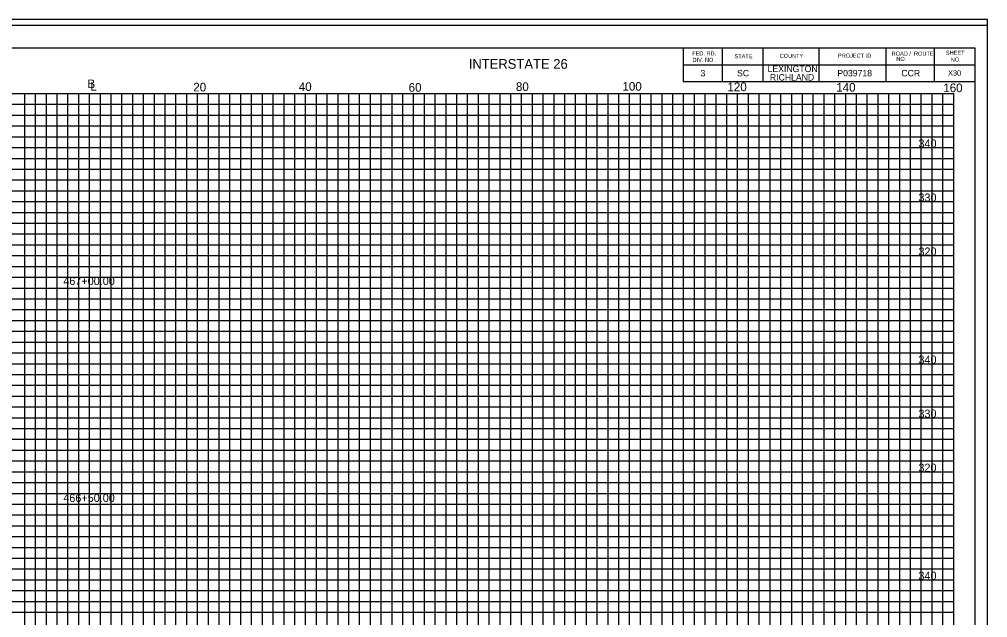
# Model space of a CAD drawing. Extents: x 967 to 1746, y 964 to 7904.
# Drawn here: x 1567 to 1746.3, y 1353 to 1463.7 of the extents above; entities that cross this region are included whole.
import ezdxf

# ---------------------------------------------------------------- set-up
doc = ezdxf.new("R2010")
doc.units = 0
for name, color, linetype in [('Default', 7, 'Continuous'), ('RD_SHT_Bndy', 7, 'Continuous'), ('RD_SHT_IplotShp', 7, 'Continuous'), ('RD_SHT_MjGrid', 7, 'Continuous'), ('RD_SHT_MnGrid', 7, 'Continuous'), ('RD_SHT_TX', 7, 'Continuous'), ('RD_Sketch1', 7, 'Continuous')]:
    doc.layers.add(name, color=color, linetype=linetype)

msp = doc.modelspace()

# ---------------------------------------------------------------- linework, layer by layer
at = {"layer": 'RD_SHT_Bndy'}
for p, q in [((1416.11, 1458.46), (1743.89, 1458.46)), ((1689.89, 1458.46), (1689.89, 1452.21)), ((1697.14, 1458.46), (1697.14, 1452.21)), ((1704.64, 1458.46), (1704.64, 1452.21)), ((1715, 1458.46), (1715, 1452.21)), ((1727.43, 1458.46), (1727.43, 1452.21)), ((1736.39, 1458.46), (1736.39, 1452.21)), ((1743.89, 1458.46), (1743.89, 1248.98)), ((1689.89, 1455.33), (1743.89, 1455.33)), ((1689.89, 1452.21), (1743.89, 1452.21))]:
    msp.add_line(p, q, dxfattribs=at)
at = {"layer": 'RD_SHT_IplotShp'}
for points in [[(1387.41, 1243.72), (1746.28, 1243.72), (1746.28, 1463.72), (1387.41, 1463.72)], [(1408.52, 1244.84), (1746.28, 1244.84), (1746.28, 1462.6), (1408.52, 1462.6)]]:
    msp.add_lwpolyline(points, close=True, dxfattribs=at)
at = {"layer": 'RD_SHT_MjGrid'}
for p, q in [((1420, 1450), (1740, 1450)), ((1570, 1280), (1570, 1450)), ((1580, 1280), (1580, 1450)), ((1590, 1280), (1590, 1450)), ((1600, 1280), (1600, 1450)), ((1610, 1280), (1610, 1450)), ((1620, 1280), (1620, 1450)), ((1630, 1280), (1630, 1450)), ((1640, 1280), (1640, 1450)), ((1650, 1280), (1650, 1450)), ((1660, 1280), (1660, 1450)), ((1670, 1280), (1670, 1450)), ((1680, 1280), (1680, 1450)), ((1690, 1280), (1690, 1450)), ((1700, 1280), (1700, 1450)), ((1710, 1280), (1710, 1450)), ((1720, 1280), (1720, 1450)), ((1730, 1280), (1730, 1450)), ((1740, 1280), (1740, 1450)), ((1420, 1440), (1740, 1440)), ((1420, 1430), (1740, 1430)), ((1420, 1420), (1740, 1420)), ((1420, 1410), (1740, 1410)), ((1420, 1400), (1740, 1400)), ((1420, 1390), (1740, 1390)), ((1420, 1380), (1740, 1380)), ((1420, 1370), (1740, 1370)), ((1420, 1360), (1740, 1360))]:
    msp.add_line(p, q, dxfattribs=at)
at = {"layer": 'RD_SHT_MnGrid'}
for p, q in [((1568, 1280), (1568, 1450)), ((1572, 1280), (1572, 1450)), ((1574, 1280), (1574, 1450)), ((1576, 1280), (1576, 1450)), ((1578, 1280), (1578, 1450)), ((1582, 1280), (1582, 1450)), ((1584, 1280), (1584, 1450)), ((1586, 1280), (1586, 1450)), ((1588, 1280), (1588, 1450)), ((1592, 1280), (1592, 1450)), ((1594, 1280), (1594, 1450)), ((1596, 1280), (1596, 1450)), ((1598, 1280), (1598, 1450)), ((1602, 1280), (1602, 1450)), ((1604, 1280), (1604, 1450)), ((1606, 1280), (1606, 1450)), ((1608, 1280), (1608, 1450)), ((1612, 1280), (1612, 1450)), ((1614, 1280), (1614, 1450)), ((1616, 1280), (1616, 1450)), ((1618, 1280), (1618, 1450)), ((1622, 1280), (1622, 1450)), ((1624, 1280), (1624, 1450)), ((1626, 1280), (1626, 1450)), ((1628, 1280), (1628, 1450)), ((1632, 1280), (1632, 1450)), ((1634, 1280), (1634, 1450)), ((1636, 1280), (1636, 1450)), ((1638, 1280), (1638, 1450)), ((1642, 1280), (1642, 1450)), ((1644, 1280), (1644, 1450)), ((1646, 1280), (1646, 1450)), ((1648, 1280), (1648, 1450)), ((1652, 1280), (1652, 1450)), ((1654, 1280), (1654, 1450)), ((1656, 1280), (1656, 1450)), ((1658, 1280), (1658, 1450)), ((1662, 1280), (1662, 1450)), ((1664, 1280), (1664, 1450)), ((1666, 1280), (1666, 1450)), ((1668, 1280), (1668, 1450)), ((1672, 1280), (1672, 1450)), ((1674, 1280), (1674, 1450)), ((1676, 1280), (1676, 1450)), ((1678, 1280), (1678, 1450)), ((1682, 1280), (1682, 1450)), ((1684, 1280), (1684, 1450)), ((1686, 1280), (1686, 1450)), ((1688, 1280), (1688, 1450)), ((1692, 1280), (1692, 1450)), ((1694, 1280), (1694, 1450)), ((1696, 1280), (1696, 1450)), ((1698, 1280), (1698, 1450)), ((1702, 1280), (1702, 1450)), ((1704, 1280), (1704, 1450)), ((1706, 1280), (1706, 1450)), ((1708, 1280), (1708, 1450)), ((1712, 1280), (1712, 1450)), ((1714, 1280), (1714, 1450)), ((1716, 1280), (1716, 1450)), ((1718, 1280), (1718, 1450)), ((1722, 1280), (1722, 1450)), ((1724, 1280), (1724, 1450)), ((1726, 1280), (1726, 1450)), ((1728, 1280), (1728, 1450)), ((1732, 1280), (1732, 1450)), ((1734, 1280), (1734, 1450)), ((1736, 1280), (1736, 1450)), ((1738, 1280), (1738, 1450)), ((1420, 1448), (1740, 1448)), ((1420, 1446), (1740, 1446)), ((1420, 1444), (1740, 1444)), ((1420, 1442), (1740, 1442)), ((1420, 1438), (1740, 1438)), ((1420, 1436), (1740, 1436)), ((1420, 1434), (1740, 1434)), ((1420, 1432), (1740, 1432)), ((1420, 1428), (1740, 1428)), ((1420, 1426), (1740, 1426)), ((1420, 1424), (1740, 1424)), ((1420, 1422), (1740, 1422)), ((1420, 1418), (1740, 1418)), ((1420, 1416), (1740, 1416)), ((1420, 1414), (1740, 1414)), ((1420, 1412), (1740, 1412)), ((1420, 1408), (1740, 1408)), ((1420, 1406), (1740, 1406)), ((1420, 1404), (1740, 1404)), ((1420, 1402), (1740, 1402)), ((1420, 1398), (1740, 1398)), ((1420, 1396), (1740, 1396)), ((1420, 1394), (1740, 1394)), ((1420, 1392), (1740, 1392)), ((1420, 1388), (1740, 1388)), ((1420, 1386), (1740, 1386)), ((1420, 1384), (1740, 1384)), ((1420, 1382), (1740, 1382)), ((1420, 1378), (1740, 1378)), ((1420, 1376), (1740, 1376)), ((1420, 1374), (1740, 1374)), ((1420, 1372), (1740, 1372)), ((1420, 1368), (1740, 1368)), ((1420, 1366), (1740, 1366)), ((1420, 1364), (1740, 1364)), ((1420, 1362), (1740, 1362)), ((1420, 1358), (1740, 1358)), ((1420, 1356), (1740, 1356)), ((1420, 1354), (1740, 1354))]:
    msp.add_line(p, q, dxfattribs=at)
at = {"layer": 'RD_Sketch1'}
msp.add_lwpolyline([(1387.41, 1243.72), (1746.28, 1243.72), (1746.28, 1463.72), (1387.41, 1463.72)], close=True, dxfattribs=at)

# ---------------------------------------------------------------- texts
at = {"layer": 'Default'}
for s, height, p in [('X30', 1, (1738.94, 1453.3)), ('340', 1.5, (1733.47, 1440)), ('330', 1.5, (1733.47, 1430)), ('320', 1.5, (1733.47, 1420)), ('467+00.00', 1.5, (1575.13, 1414.55)), ('340', 1.5, (1733.47, 1400)), ('330', 1.5, (1733.47, 1390)), ('320', 1.5, (1733.47, 1380)), ('466+50.00', 1.5, (1575.13, 1374.4)), ('340', 1.5, (1733.47, 1360))]:
    msp.add_text(s, height=height, dxfattribs=at).set_placement(p)
at = {"layer": 'RD_SHT_TX'}
for s, height, p in [('FED. RD.', 0.75, (1691.58, 1457.05)), ('ROAD /  ROUTE', 0.75, (1728.51, 1457.01)), ('SHEET', 0.75, (1738.56, 1457.16)), ('DIV. NO.', 0.75, (1691.64, 1455.86)), ('STATE', 0.75, (1699.41, 1456.53)), ('COUNTY', 0.75, (1707.78, 1456.59)), ('PROJECT ID', 0.75, (1718.58, 1456.63)), ('   NO.', 0.75, (1728.51, 1456.03)), ('NO.', 0.75, (1739.45, 1455.91)), ('3', 1.2, (1693.12, 1453.17)), ('SC', 1.2, (1699.89, 1453.17)), ('LEXINGTON', 1.2, (1705.54, 1453.96)), ('P039718', 1.2, (1718.46, 1453.17)), ('CCR', 1.2, (1730.31, 1453.17)), ('B', 1.6, (1579.61, 1450.99)), ('RICHLAND', 1.2, (1705.97, 1452.39)), ('L', 1.6, (1580.12, 1450.54)), ('20', 1.6, (1599.2, 1450.38)), ('40', 1.6, (1618.74, 1450.47)), ('60', 1.6, (1639.08, 1450.33)), ('80', 1.6, (1658.94, 1450.47)), ('100', 1.6, (1678.67, 1450.53)), ('120', 1.6, (1698.11, 1450.43)), ('140', 1.6, (1718.26, 1450.34)), ('160', 1.6, (1738.08, 1450.25))]:
    msp.add_text(s, height=height, dxfattribs=at).set_placement(p)
msp.add_text('INTERSTATE 26', height=1.8, rotation=0, dxfattribs=at).set_placement((1650.21, 1454.58))

doc.saveas('drawing.dxf')
